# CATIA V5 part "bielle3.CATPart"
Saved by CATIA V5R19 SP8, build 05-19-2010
Part number: Pièce3
Bounding box of the stored display mesh (mm): x -20 to 26.998, y -12.442 to 532.52, z -532.628 to 12.442
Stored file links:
  G:\EU_thinkMotion\CFAO_2010\SIL_groupe1\SIL_groupe1\A reprendre\lalpha\lalpha\Alpha.mécanisme\bielle3.CATPart
  G:\EU_thinkMotion\CFAO_2010\SIL_groupe1\SIL_groupe1\A reprendre\lalpha\lalpha\Alpha.mécanisme\Mecanisme_final.CATProduct
  G:\EU_thinkMotion\CFAO_2010\SIL_groupe1\SIL_groupe1\A reprendre\lalpha\lalpha\Alpha.mécanisme\bielle5.CATPart
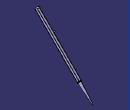
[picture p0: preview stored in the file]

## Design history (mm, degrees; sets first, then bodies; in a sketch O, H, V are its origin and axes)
Set1
  Sketch1, origin (20, 213.7665, -594.7665), H (-1, 0, 0), V (0, 0.7071, 0.7071), geometry linked from another document
Body1 (main body)
  Line1: stored without definition
  Line2: stored without definition
  Sketch2 on Line1, origin (0, -268.3345, 268.3345), H (0, 0.7071, -0.7071), V (0, 0.7071, 0.7071)
    line L1 (379.4974, -12.5) -> (951.2015, -12.5)
    line L2 (951.2015, -12.5) -> (951.2015, 12.5)
    line L3 (951.2015, 12.5) -> (379.4974, 12.5)
    arc A1 centre (379.4974, 0) radius 12.5 from (379.4974, 12.5) to (379.4974, -12.5) ccw
    point P6 (366.9974, 0)
    horizontal: L1 H, L3 H
    vertical: L2 V
    tangency: A1 L3
    coincidence: A1 P6, P6 H
  Pad1: profile Sketch2, direction (1, 0, 0), length 20
  Line3: stored without definition
  Line4: stored without definition
  Sketch3 on Line3, origin (0, -268.3345, 268.3345), H (0, 0.7071, -0.7071), V (0, 0.7071, 0.7071)
    circle A1 centre (570.263, 0) radius 5
    point P1 (570.263, 0)
    coincidence: P1 H
  Pad2: profile Sketch3, direction (-1, 0, 0), length 20
  Line5: stored without definition
  Line6: stored without definition
  Sketch4 on Line5, origin (0, -268.3345, 268.3345), H (0, 0.7071, -0.7071), V (0, 0.7071, 0.7071)
    circle A1 centre (379.4806, 0) radius 5
    point P1 (379.4806, 0)
    coincidence: P1 H
  Pad3: profile Sketch4, direction (-1, 0, 0), length 20
  Plane1: type Offset, RefPlane end face of Pad1, Offset -10, reversed
  Sketch5 on Plane1, origin (10, 0, 0), H (0, -1, 0), V (0, 0, 1)
    line L1 (-399.8804, -399.9027) -> (-412.0837, -387.9896)
    line L2 (-417.4887, -393.5263) -> (-414.5661, -396.3793)
    line L3 (-417.4887, -393.5263) -> (-412.0837, -387.9896)
    line L4 (-414.5661, -396.3793) -> (-533.2479, -530.269)
    line L5 (-531.6108, -531.7201) -> (-533.2479, -530.269)
    line L6 (-531.6108, -531.7201) -> (-399.8804, -399.9027)
    parallelism: L2 L1
    perpendicularity: L3 L1, L5 L4
  Shaft1: profile Sketch5, axis Sketch5.L6, angle 360
  Chamfer1: length 1, angle 45, on edge [face of Shaft1 from Sketch5.L2 | face of Shaft1 from Sketch5.L3]
  Chamfer2: length 1, angle 45, on edge [face of Shaft1 from Sketch5.L3 | face of Shaft1 from Sketch5.L1]
  Chamfer3: length 1, angle 45, on edge [face of Shaft1 from Sketch5.L5 | face of Shaft1 from Sketch5.L4]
